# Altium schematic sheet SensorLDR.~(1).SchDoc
size A
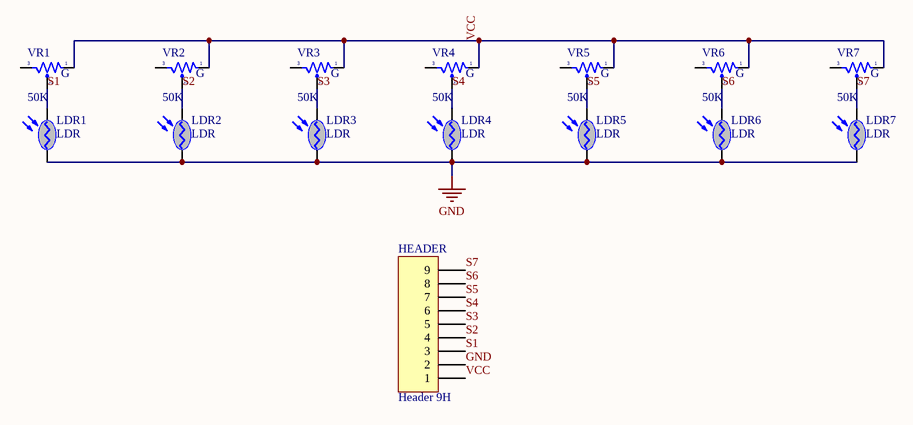
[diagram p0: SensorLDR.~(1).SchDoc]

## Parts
HEADER  Header 9H  [HDR1X9H]
LDR1  LDR  [CDS]
LDR2  LDR  [CDS]
LDR3  LDR  [CDS]
LDR4  LDR  [CDS]
LDR5  LDR  [CDS]
LDR6  LDR  [CDS]
LDR7  LDR  [CDS]
VR1  50K  [VR-S1]
VR2  50K  [VR-S1]
VR3  50K  [VR-S1]
VR4  50K  [VR-S1]
VR5  50K  [VR-S1]
VR6  50K  [VR-S1]
VR7  50K  [VR-S1]

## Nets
GND: HEADER.2 LDR1.1(A) LDR2.1(A) LDR3.1(A) LDR4.1(A) LDR5.1(A) LDR6.1(A) LDR7.1(A)
S1: HEADER.3 LDR1.2(K) VR1.2
S2: HEADER.4 LDR2.2(K) VR2.2
S3: HEADER.5 LDR3.2(K) VR3.2
S4: HEADER.6 LDR4.2(K) VR4.2
S5: HEADER.7 LDR5.2(K) VR5.2
S6: HEADER.8 LDR6.2(K) VR6.2
S7: HEADER.9 LDR7.2(K) VR7.2
VCC: HEADER.1 VR1.1 VR2.1 VR3.1 VR4.1 VR5.1 VR6.1 VR7.1

Not connected (* = marked no-connect by the designer): VR1 3; VR2 3; VR3 3; VR4 3; VR5 3; VR6 3; VR7 3

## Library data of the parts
HEADER = Header 9H: Header, 9-Pin, Right Angle
LDR1-LDR7 = LDR: Quang Tro
VR1-VR7 = VR-S: Var Resistor; Value: Volume 50k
